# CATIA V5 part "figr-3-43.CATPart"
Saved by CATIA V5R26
Part number: Part1
Bounding box of the stored display mesh (mm): x 0 to 0, y -151.508 to 68.716, z -53.883 to 66.715
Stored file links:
  D:\_Deepak\CATIA\CATIA V5 2015 Parts Files\Part files\Partfiles\c03_catia_v5_6r2015_prt\figr-3-43.CATPart
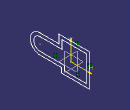
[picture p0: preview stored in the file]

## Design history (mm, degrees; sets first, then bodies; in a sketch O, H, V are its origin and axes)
Body1 (main body)
  Sketch1 on yz-plane, origin (0, 0, 0), H (0, 1, 0), V (0, 0, 1)
    point P1 (-23.9446, -41.7966)
    line L1 (-23.9446, -41.7966) -> (-23.9446, -23.995)
    line L2 (-23.9446, -23.995) -> (-115.8106, -23.995)
    arc A1 centre (-115.8106, -0.3669) radius 23.6281 from (-115.8106, -23.995) to (-115.8106, 23.2613) cw
    line L3 (-115.8106, 23.2613) -> (-33.6641, 23.2613)
    line L4 (-33.6641, 23.2613) -> (-33.6641, 54.6279)
    line L5 (-33.6641, 54.6279) -> (56.6292, 54.6279)
    line L6 (56.6292, 54.6279) -> (56.6292, -41.7966)
    line L7 (56.6292, -41.7966) -> (-23.9446, -41.7966)
    point P10 (-23.9446, -41.7966)
    line L8 (68.7159, 66.7146) -> (68.7159, -53.8833)
    line L9 (68.7159, -53.8833) -> (-36.0313, -53.8833)
    line L10 (-36.0313, -53.8833) -> (-36.0313, -36.0817)
    line L11 (-36.0313, -36.0817) -> (-115.8105, -36.0817)
    arc A2 centre (-115.8106, -0.3669) radius 35.7148 from (-115.8105, 35.348) to (-115.8105, -36.0817) ccw
    line L12 (-115.8105, 35.348) -> (-45.7508, 35.348)
    line L13 (-45.7508, 35.348) -> (-45.7508, 66.7146)
    line L14 (-45.7508, 66.7146) -> (68.7159, 66.7146)
    curve C1
    vertical: L1 V, L4 V, L6 V
    horizontal: L2 H, L5 H, L7 H
    tangency: A1 L2, L3 A1
    coincidence: P10 L1, P1 P10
